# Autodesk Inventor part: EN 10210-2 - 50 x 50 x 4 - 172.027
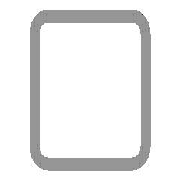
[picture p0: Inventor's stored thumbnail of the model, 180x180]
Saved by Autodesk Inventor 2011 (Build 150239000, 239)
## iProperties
IsCustomPart: 1
Created: 2010-02
Part Number: EN 10210-2 - 50 x 50 x 4 - 172.027
Material: Steel, Mild
Description: Tube 50*50*4
Document SubType Name: Modeling
Standard: DIN
Designer: PC
Standard Revision: 1997
Standards Organization: DIN
Language: en-US
Size Designation: 50 x 50 x 4
Categories: <MemberInstance><Categories><Category DisplayName="Structural Shapes" InternalName="089c4875-fa83-4c05-b084-43b9cc11f5ed" Mnemonic="GRDR"><CategoryParameter Dis
Stock Number: 50 x 50 x 4
Density: 7.86 g/cm^3
_CCFamilyMember: 15
_CCFamilyDisplayName: DIN EN 10210-2 (Square) - Tube
_FrameMemberDoc: Frame Member File
_Version: 15.0.0
_GetPNFromCC: 1
G_L: 172.027 mm
G_W: 50.000 mm
G_H: 50.000 mm
+8F47155D-A87E-4112-8D2F-1C518DD12035+CUTDETAIL1: Cut
Author: PC
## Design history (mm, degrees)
node "Start plane"
node "End plane"
sketch "Sketch"
  geometry: L1 (-25, -19)-(-25, 19); L2 (-19, 25)-(19, 25); L3 (25, 19)-(25, -19); L4 (19, -25)-(-19, -25); L5 (-19, 21)-(19, 21); L6 (21, 19)-(21, -19); L7 (19, -21)-(-19, -21); L8 (-21, -19)-(-21, 19); L9 (0, 36.74)-(0, -36.74) reference; L10 (-36.74, 0)-(36.74, 0) reference; A1 r 6 centre (-19, -19) between (-25, -19) and (-19, -25); A2 r 6 centre (-19, 19) between (-19, 25) and (-25, 19); A3 r 6 centre (19, 19) between (25, 19) and (19, 25); A4 r 6 centre (19, -19) between (19, -25) and (25, -19); A5 r 2 centre (-19, 19) between (-19, 21) and (-21, 19); A6 r 2 centre (19, 19) between (21, 19) and (19, 21); A7 r 2 centre (19, -19) between (19, -21) and (21, -19); A8 r 2 centre (-19, -19) between (-21, -19) and (-19, -21)
  constraints: 16 end point, 16 point on circle, 8 centre point, 8 tangent, 4 parallel, 3 equal radius, 2 perpendicular, 7 other
  dimensions: "d7" = 6 radius of A1 (= G_IR); "d10" = 50 distance between parallel lines of L2 L4 (= G_H); "d11" = 50 distance between parallel lines of L1 L3 (= G_W); "d12" = 4 distance between parallel lines of L3 L6 (= G_T); "d15" = 25 distance between parallel lines of L2 L10 (= 0.5 x d10); "d16" = 25 distance between parallel lines of L9 L3 (= 0.5 x d11)
extrude "Body" new body sketch "Sketch" stored distance "d3" = 172.02704 (= G_L); taper "d4" = 0 deg
node "Driven Length"
  sketch "Sketch3"
    geometry: L1 (0, 0)-(10, 0) reference
    constraints: 2 end point, 1 horizontal
  workplane "Work Plane3"
  sketch "Sketch4"
    geometry: L1 (-2, -7.027)-(12, -7.027) reference; L2 (-2, 165)-(12, 165) reference
    dimensions: "d18" = 172.02704 distance between parallel lines of L1 L2 (derived)
workplane "Work Plane4"
split "Split1"
body "Solid1"
other parameters: "G_W" = 50 [user parameter; used in 1 equation term], "G_H" = 50 [user parameter; used in 1 equation term], "G_T" = 4 [user parameter; used in 1 equation term], "G_IR" = 6 [user parameter; used in 1 equation term], "G_L" = 172.02704 (= d18) [user parameter; used in 1 equation term], "G_OFFSET_START" = 7.02704 [user parameter; used in 1 equation term], "G_OFFSET_END" = 0 [user parameter; used in 1 equation term], "d13" = -7.02704 (= -G_OFFSET_START), "d14" = 165 (= G_OFFSET_END + B_L), "B_L" = 165 [user parameter; used in 1 equation term], "d17" = 90 deg
